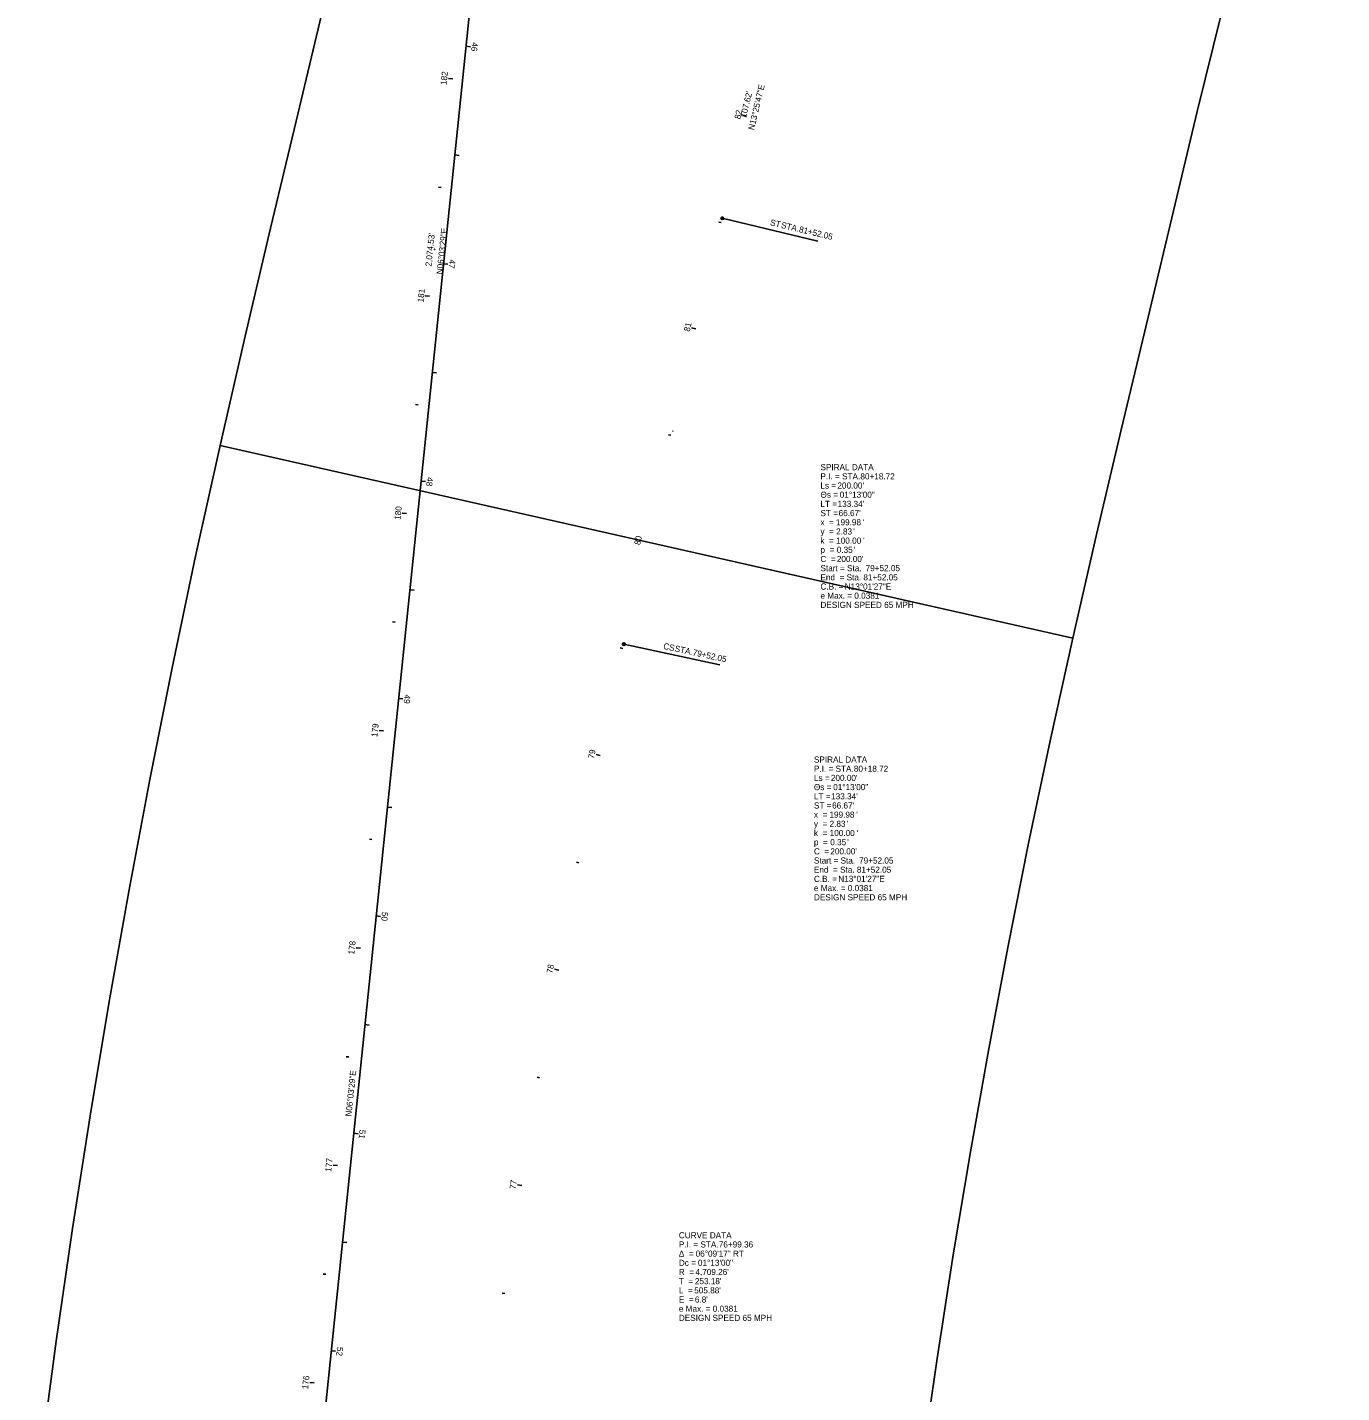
# Model space of a CAD drawing. Extents: x 172043 to 172958, y 249504 to 260295.
# Drawn here: x 172096 to 172697, y 254530 to 255155 of the extents above; entities that cross this region are included whole.
import ezdxf

# ---------------------------------------------------------------- set-up
doc = ezdxf.new("R2010")
doc.units = 0
for name, color, linetype in [('DR_X_Cells', 7, 'Continuous'), ('DR_X_Storm_Sewer', 7, 'Continuous'), ('PV_X_Curb', 7, 'Continuous'), ('PV_X_EOP', 7, 'Continuous'), ('RS_Raster1', 7, 'Continuous'), ('RW_X_CL_100_Bearings', 7, 'Continuous'), ('RW_X_CL_100_Cardinal_Points', 7, 'Continuous'), ('RW_X_CL_100_Curve_Data', 7, 'Continuous'), ('RW_X_CL_100_Distances', 7, 'Continuous'), ('RW_X_CL_100_Stations', 7, 'Continuous'), ('SC_Scratch1', 7, 'Continuous')]:
    doc.layers.add(name, color=color, linetype=linetype)

msp = doc.modelspace()

# ---------------------------------------------------------------- linework, layer by layer
at = {"layer": 'DR_X_Cells'}
for centre in [(172282.32, 255053.46), (172282.32, 255053.46), (172391.42, 254970.22)]:
    msp.add_circle(centre, 0.05, dxfattribs=at)
at = {"layer": 'DR_X_Storm_Sewer'}
for points in [[(172184.15, 254963.66), (172574.32, 254875.56), (172585.22, 254922.95), (172596.48, 254970.85), (172608.01, 255019.19), (172619.62, 255067.83), (172631.23, 255116.46), (172642.23, 255160.89), (172654.11, 255204.05), (172667.12, 255246.88), (172681.24, 255289.36), (172697.36, 255334.65), (172320.75, 255469.43), (172303.35, 255420.51), (172285.92, 255368.09), (172269.88, 255315.24), (172255.22, 255261.99), (172242.17, 255209.36), (172230.56, 255160.73), (172218.95, 255112.1), (172207.28, 255063.17), (172195.65, 255013.72)], [(172095.96, 254450.44), (172493.22, 254403.68), (172499.07, 254451.2), (172505.42, 254498.65), (172512.28, 254546.03), (172519.63, 254593.34), (172527.5, 254640.57), (172535.86, 254687.71), (172544.72, 254734.76), (172554.08, 254781.71), (172563.94, 254828.56), (172574.32, 254875.56), (172184.15, 254963.66), (172172.96, 254913.01), (172162.22, 254862), (172152.03, 254810.88), (172142.38, 254759.66), (172133.28, 254708.34), (172124.72, 254656.92), (172116.71, 254605.42), (172109.24, 254553.83), (172102.33, 254502.17)]]:
    msp.add_lwpolyline(points, close=True, dxfattribs=at)
at = {"layer": 'PV_X_EOP'}
for p, q in [((172290.59, 255131.42), (172288.61, 255131.63)), ((172285.32, 255081.7), (172284.12, 255081.82)), ((172280.04, 255031.97), (172278.05, 255032.19)), ((172274.76, 254982.25), (172273.57, 254982.38)), ((172269.49, 254932.53), (172267.5, 254932.74)), ((172264.21, 254882.81), (172263.02, 254882.94)), ((172258.93, 254833.09), (172256.94, 254833.3)), ((172253.66, 254783.37), (172252.46, 254783.5)), ((172248.38, 254733.65), (172246.39, 254733.86)), ((172243.1, 254683.93), (172241.91, 254684.06)), ((172237.83, 254634.21), (172235.84, 254634.42)), ((172232.55, 254584.49), (172231.36, 254584.61)), ((172227.27, 254534.77), (172225.28, 254534.98))]:
    msp.add_line(p, q, dxfattribs=at)
at = {"layer": 'RW_X_CL_100_Bearings'}
for p, q in [((172413.95, 255067.64), (172457.72, 255057.19)), ((172368.88, 254872.79), (172412.86, 254863.27))]:
    msp.add_line(p, q, dxfattribs=at)
for centre in [(172413.95, 255067.64), (172368.88, 254872.79)]:
    msp.add_circle(centre, 0.6, dxfattribs=at)
at = {"layer": 'RW_X_CL_100_Stations'}
for p, q in [((172425.09, 255114.28), (172423.14, 255114.74)), ((172413.48, 255065.64), (172412.31, 255065.92)), ((172401.89, 255017.01), (172399.94, 255017.47)), ((172390.43, 254968.34), (172389.27, 254968.61)), ((172379.24, 254919.6), (172377.29, 254920.04)), ((172368.45, 254870.78), (172367.27, 254871.04)), ((172358.15, 254821.86), (172356.19, 254822.26)), ((172348.38, 254772.82), (172347.2, 254773.05)), ((172339.12, 254723.69), (172337.15, 254724.05)), ((172330.39, 254674.45), (172329.2, 254674.66)), ((172322.18, 254625.13), (172320.2, 254625.45)), ((172314.49, 254575.73), (172313.31, 254575.91))]:
    msp.add_line(p, q, dxfattribs=at)
at = {"layer": 'SC_Scratch1'}
for p, q in [((172428.67, 256423.35), (172177.28, 253990.91)), ((172409.1, 256234.03), (172171.47, 253934.66)), ((172296.69, 255146.34), (172298.68, 255146.14)), ((172296.69, 255146.34), (172298.68, 255146.14)), ((172291.55, 255096.61), (172293.54, 255096.4)), ((172286.41, 255046.87), (172288.4, 255046.67)), ((172286.41, 255046.87), (172288.4, 255046.67)), ((172281.27, 254997.14), (172283.26, 254996.93)), ((172276.13, 254947.4), (172278.12, 254947.2)), ((172270.99, 254897.67), (172272.98, 254897.46)), ((172265.85, 254847.93), (172267.84, 254847.73)), ((172260.71, 254798.2), (172262.7, 254797.99)), ((172255.57, 254748.46), (172257.56, 254748.26)), ((172250.43, 254698.73), (172252.42, 254698.52)), ((172245.29, 254648.99), (172247.28, 254648.78)), ((172240.15, 254599.26), (172242.14, 254599.05)), ((172235.01, 254549.52), (172237, 254549.31))]:
    msp.add_line(p, q, dxfattribs=at)

# ---------------------------------------------------------------- texts
at = {"layer": 'PV_X_Curb'}
msp.add_text("2,074.53'", height=2.8, rotation=83.94188, dxfattribs=at).set_placement((172280.85, 255045.47))
at = {"layer": 'PV_X_EOP'}
for s, p in [('182', (172287.77, 255128.49)), ('181', (172277.21, 255029.03)), ('180', (172266.66, 254929.55)), ('179', (172256.11, 254830.15)), ('178', (172245.55, 254730.68)), ('177', (172235, 254631.25)), ('176', (172224.44, 254531.79))]:
    msp.add_text(s, height=2.8, rotation=83.94188, dxfattribs=at).set_placement(p)
at = {"layer": 'RS_Raster1'}
msp.add_text('N13°25\'47"E', height=2.8, rotation=76.57039, dxfattribs=at).set_placement((172428.48, 255107.81))
at = {"layer": 'RW_X_CL_100_Bearings'}
for s, rotation, p in [('ST', 346.57039, (172435.65, 255064.5)), (' STA. ', 346.57039, (172439.65, 255063.55)), ('81+52.05', 346.57039, (172448.84, 255061.35)), ('CS', 347.78705, (172386.77, 254870.67)), (' STA. ', 347.78705, (172390.97, 254869.76)), ('79+52.05', 347.78705, (172400.21, 254867.76))]:
    msp.add_text(s, height=2.8, rotation=rotation, dxfattribs=at).set_placement(p)
at = {"layer": 'RW_X_CL_100_Cardinal_Points'}
for s, p in [('SPIRAL DATA', (172458.87, 254952.37)), ('P.I. = STA. ', (172458.87, 254948.17)), ('80+18.72', (172477.14, 254948.17)), ('Θs = ', (172458.87, 254939.77)), ('Ls = ', (172458.87, 254943.97)), ("200.00'", (172466.63, 254943.97)), ('01°13\'00"', (172467.68, 254939.77)), ('LT = ', (172458.87, 254935.57)), ("133.34'", (172466.73, 254935.57)), ('ST = ', (172458.87, 254931.37)), ('199.98', (172465.97, 254927.17)), ("66.67'", (172467.18, 254931.37)), ("'", (172478.26, 254927.17)), ('y  = ', (172458.87, 254922.97)), ('x  = ', (172458.87, 254927.17)), ('2.83', (172466.04, 254922.97)), ("'", (172473.85, 254922.97)), ('k  = ', (172458.87, 254918.77)), ('100.00', (172466.07, 254918.77)), ('0.35', (172466.33, 254914.57)), ("'", (172474.15, 254914.57)), ("'", (172478.36, 254918.77)), ('C  = ', (172458.87, 254910.37)), ('p  = ', (172458.87, 254914.57)), ("200.00'", (172466.37, 254910.37)), ('Start = Sta. ', (172458.87, 254906.17)), ('End  = Sta. ', (172458.87, 254901.97)), ('81+52.05', (172478.51, 254901.97)), ('79+52.05', (172479.53, 254906.17)), ('C.B. = ', (172458.87, 254897.77)), ('N13°01\'27"E', (172470, 254897.77)), ('e Max. = 0.0381', (172458.87, 254893.57)), ('DESIGN SPEED 65 MPH', (172458.87, 254889.37)), ('SPIRAL DATA', (172455.89, 254818.6)), ('P.I. = STA. ', (172455.89, 254814.4)), ('80+18.72', (172474.16, 254814.4)), ('Ls = ', (172455.89, 254810.2)), ("200.00'", (172463.65, 254810.2)), ('Θs = ', (172455.89, 254806)), ('01°13\'00"', (172464.69, 254806)), ('ST = ', (172455.89, 254797.6)), ('LT = ', (172455.89, 254801.8)), ("133.34'", (172463.75, 254801.8)), ("66.67'", (172464.2, 254797.6)), ('x  = ', (172455.89, 254793.4)), ('199.98', (172462.99, 254793.4)), ("'", (172475.28, 254793.4)), ('y  = ', (172455.89, 254789.2)), ('k  = ', (172455.89, 254785)), ('2.83', (172463.05, 254789.2)), ('100.00', (172463.09, 254785)), ("'", (172470.87, 254789.2)), ("'", (172475.37, 254785)), ('p  = ', (172455.89, 254780.8)), ('0.35', (172463.35, 254780.8)), ("'", (172471.17, 254780.8)), ('Start = Sta. ', (172455.89, 254772.4)), ('C  = ', (172455.89, 254776.6)), ("200.00'", (172463.39, 254776.6)), ('79+52.05', (172476.55, 254772.4)), ('End  = Sta. ', (172455.89, 254768.2)), ('81+52.05', (172475.53, 254768.2)), ('e Max. = 0.0381', (172455.89, 254759.8)), ('C.B. = ', (172455.89, 254764)), ('N13°01\'27"E', (172467.02, 254764)), ('DESIGN SPEED 65 MPH', (172455.89, 254755.6)), ('CURVE DATA', (172394.08, 254600.96)), ('P.I. = STA. ', (172394.08, 254596.76)), ('76+99.36', (172412.35, 254596.76)), ('Δ  = ', (172394.08, 254592.56)), ('06°09\'17" RT', (172401.76, 254592.56)), ('Dc = ', (172394.08, 254588.36)), ('R  = ', (172394.08, 254584.16)), ("4,709.26'", (172401.66, 254584.16)), ('01°13\'00"', (172402.82, 254588.36)), ('T  = ', (172394.08, 254579.96)), ("253.18'", (172401.42, 254579.96)), ('L  = ', (172394.08, 254575.76)), ('E  = ', (172394.08, 254571.56)), ("505.88'", (172401.12, 254575.76)), ("6.8'", (172401.42, 254571.56)), ('e Max. = 0.0381', (172394.08, 254567.36)), ('DESIGN SPEED 65 MPH', (172394.08, 254563.16))]:
    msp.add_text(s, height=2.8, dxfattribs=at).set_placement(p)
at = {"layer": 'RW_X_CL_100_Curve_Data'}
msp.add_text("107.62'", height=2.8, rotation=76.57039, dxfattribs=at).set_placement((172424.86, 255113.49))
at = {"layer": 'RW_X_CL_100_Distances'}
for p in [(172285.92, 255041.89), (172244.24, 254656.54)]:
    msp.add_text('N06°03\'29"E', height=2.8, rotation=83.94188, dxfattribs=at).set_placement(p)
at = {"layer": 'RW_X_CL_100_Stations'}
for s, rotation, p in [('82', 76.57039, (172422.15, 255112.76)), ('81', 76.65281, (172398.99, 255015.6)), ('80', 77.27364, (172376.31, 254917.98)), ('79', 78.42038, (172355.26, 254820.2)), ('78', 79.63704, (172336.26, 254721.95)), ('77', 80.8537, (172319.34, 254623.26))]:
    msp.add_text(s, height=2.8, rotation=rotation, dxfattribs=at).set_placement(p)
at = {"layer": 'SC_Scratch1'}
for s, p in [('46', (172299.41, 255148.31)), ('47', (172289.13, 255048.9)), ('48', (172278.85, 254949.35)), ('49', (172268.56, 254849.86)), ('50', (172258.29, 254750.42)), ('51', (172247.99, 254650.76)), ('52', (172237.72, 254551.41))]:
    msp.add_text(s, height=2.8, rotation=264.09958, dxfattribs=at).set_placement(p)

doc.saveas('drawing.dxf')
